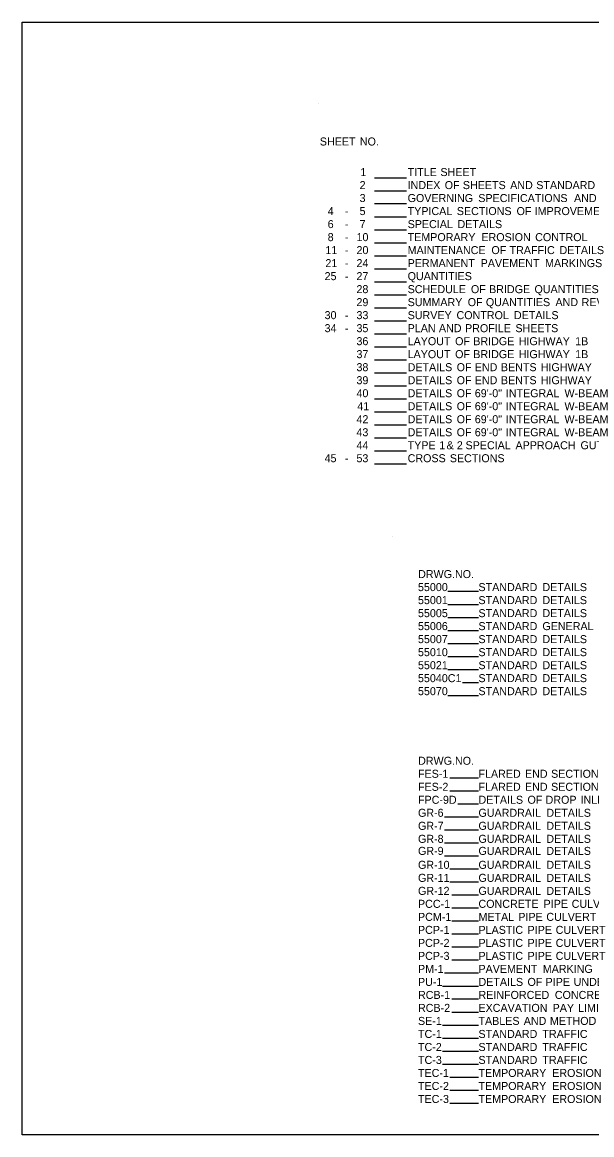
# Model space of a CAD drawing. Extents: x 1955683 to 1956002, y 566394 to 566602.
# Drawn here: x 1955683.4 to 1955790.1, y 566393.5 to 566602 of the extents above; entities that cross this region are included whole.
import ezdxf

# ---------------------------------------------------------------- set-up
doc = ezdxf.new("R2010")
doc.units = 0
doc.layers.add('Default', color=7, linetype='Continuous')
doc.layers.add('R_Border Prem', color=7, linetype='Continuous')

msp = doc.modelspace()

# ---------------------------------------------------------------- linework, layer by layer
at = {"layer": 'Default'}
for p, q in [((1955738.89, 566586.74), (1955738.89, 566586.74)), ((1955749.37, 566572.85), (1955755.35, 566572.85)), ((1955749.37, 566570.41), (1955755.35, 566570.41)), ((1955749.37, 566567.98), (1955755.35, 566567.98)), ((1955749.37, 566565.54), (1955755.35, 566565.54)), ((1955749.37, 566563.1), (1955755.35, 566563.1)), ((1955749.37, 566560.66), (1955755.35, 566560.66)), ((1955749.37, 566558.23), (1955755.35, 566558.23)), ((1955749.37, 566555.79), (1955755.35, 566555.79)), ((1955749.37, 566553.35), (1955755.35, 566553.35)), ((1955749.37, 566550.91), (1955755.35, 566550.91)), ((1955749.37, 566548.48), (1955755.35, 566548.48)), ((1955749.37, 566546.04), (1955755.35, 566546.04)), ((1955749.37, 566543.6), (1955755.35, 566543.6)), ((1955749.37, 566541.16), (1955755.35, 566541.16)), ((1955749.37, 566538.73), (1955755.35, 566538.73)), ((1955749.37, 566536.29), (1955755.35, 566536.29)), ((1955749.37, 566533.85), (1955755.35, 566533.85)), ((1955749.37, 566531.41), (1955755.35, 566531.41)), ((1955749.37, 566528.98), (1955755.35, 566528.98)), ((1955749.37, 566526.54), (1955755.35, 566526.54)), ((1955749.37, 566524.1), (1955755.35, 566524.1)), ((1955749.37, 566521.66), (1955755.35, 566521.66)), ((1955749.37, 566519.23), (1955755.35, 566519.23)), ((1955752.77, 566505.68), (1955752.77, 566505.68)), ((1955763.1, 566495.34), (1955768.86, 566495.34)), ((1955763.1, 566492.9), (1955768.86, 566492.9)), ((1955763.1, 566490.46), (1955768.86, 566490.46)), ((1955763.1, 566488.02), (1955768.86, 566488.02)), ((1955763.1, 566485.59), (1955768.86, 566485.59)), ((1955763.1, 566483.15), (1955768.86, 566483.15)), ((1955763.1, 566480.71), (1955768.86, 566480.71)), ((1955765.85, 566478.27), (1955768.86, 566478.27)), ((1955763.1, 566475.84), (1955768.86, 566475.84)), ((1955763.47, 566460.38), (1955768.86, 566460.38)), ((1955763.47, 566457.95), (1955768.86, 566457.95)), ((1955764.98, 566455.51), (1955768.86, 566455.51)), ((1955762.51, 566453.07), (1955768.86, 566453.07)), ((1955762.51, 566450.63), (1955768.86, 566450.63)), ((1955762.51, 566448.2), (1955768.86, 566448.2)), ((1955762.51, 566445.76), (1955768.86, 566445.76)), ((1955763.47, 566443.32), (1955768.86, 566443.32)), ((1955763.47, 566440.88), (1955768.86, 566440.88)), ((1955763.87, 566438.45), (1955768.86, 566438.45)), ((1955763.87, 566436.01), (1955768.86, 566436.01)), ((1955763.87, 566433.57), (1955768.86, 566433.57)), ((1955763.87, 566431.13), (1955768.86, 566431.13)), ((1955763.87, 566428.7), (1955768.86, 566428.7)), ((1955763.87, 566426.26), (1955768.86, 566426.26)), ((1955762.51, 566423.82), (1955768.86, 566423.82)), ((1955762.13, 566421.38), (1955768.86, 566421.38)), ((1955763.87, 566418.95), (1955768.86, 566418.95)), ((1955763.87, 566416.51), (1955768.86, 566416.51)), ((1955762.13, 566414.07), (1955768.86, 566414.07)), ((1955762.13, 566411.63), (1955768.86, 566411.63)), ((1955762.13, 566409.2), (1955768.86, 566409.2)), ((1955762.13, 566406.76), (1955768.86, 566406.76)), ((1955763.47, 566404.32), (1955768.86, 566404.32)), ((1955763.47, 566401.88), (1955768.86, 566401.88)), ((1955763.47, 566399.45), (1955768.86, 566399.45))]:
    msp.add_line(p, q, dxfattribs=at)
at = {"layer": 'R_Border Prem'}
msp.add_lwpolyline([(1956002.45, 566561.79), (1956002.45, 566393.51), (1955683.38, 566393.51), (1955683.38, 566601.97), (1955920.19, 566601.97), (1955920.19, 566592.09), (1955955.71, 566592.09), (1955955.71, 566588.52), (1955959.35, 566588.52), (1955959.35, 566589.17), (1955974.89, 566589.17)], dxfattribs=at)

# ---------------------------------------------------------------- texts
at = {"layer": 'Default'}
for s, p in [('SHEET', (1955739.14, 566578.88)), (' NO.', (1955746.08, 566578.88)), ('1', (1955746.73, 566573.15)), ('TITLE', (1955755.59, 566573.15)), (' SHEET', (1955761.18, 566573.15)), ('2', (1955746.59, 566570.71)), ('INDEX', (1955755.59, 566570.71)), (' OF', (1955761.98, 566570.71)), (' SHEETS', (1955765.38, 566570.71)), (' AND', (1955774.24, 566570.71)), (' STANDARD', (1955779.13, 566570.71)), ('3', (1955746.59, 566568.28)), ('GOVERNING', (1955755.59, 566568.28)), (' SPECIFICATIONS', (1955768.27, 566568.28)), (' AND', (1955786.21, 566568.28)), ('4', (1955740.62, 566565.84)), ('-', (1955743.82, 566565.84)), ('5', (1955746.58, 566565.84)), ('TYPICAL', (1955755.59, 566565.84)), (' SECTIONS', (1955764.25, 566565.84)), (' OF', (1955775.44, 566565.84)), (' IMPROVEMENT', (1955778.84, 566565.84)), ('6', (1955740.61, 566563.4)), ('7', (1955746.59, 566563.4)), ('SPECIAL', (1955755.59, 566563.4)), (' DETAILS', (1955764.37, 566563.4)), ('8', (1955740.61, 566560.96)), ('-', (1955743.82, 566563.4)), ('10', (1955746.01, 566560.96)), ('TEMPORARY', (1955755.59, 566560.96)), (' EROSION', (1955768.85, 566560.96)), (' CONTROL', (1955778.93, 566560.96)), ('-', (1955743.82, 566560.96)), ('11', (1955740.18, 566558.53)), ('-', (1955743.82, 566558.53)), ('20', (1955746.01, 566558.53)), ('MAINTENANCE', (1955755.59, 566558.53)), (' OF', (1955770.73, 566558.53)), (' TRAFFIC', (1955774.13, 566558.53)), (' DETAILS', (1955783.48, 566558.53)), ('21', (1955740.18, 566556.09)), ('-', (1955743.82, 566556.09)), ('24', (1955746.01, 566556.09)), ('PERMANENT', (1955755.59, 566556.09)), (' PAVEMENT', (1955768.71, 566556.09)), (' MARKINGS', (1955780.78, 566556.09)), ('25', (1955740.03, 566553.65)), ('-', (1955743.82, 566553.65)), ('27', (1955746, 566553.65)), ('QUANTITIES', (1955755.59, 566553.65)), ('28', (1955746, 566551.21)), ('SCHEDULE', (1955755.59, 566551.21)), (' OF', (1955766.89, 566551.21)), (' BRIDGE', (1955770.29, 566551.21)), (' QUANTITIES', (1955778.8, 566551.21)), ('29', (1955746, 566548.78)), ('SUMMARY', (1955755.59, 566548.78)), (' OF', (1955766.29, 566548.78)), (' QUANTITIES', (1955769.69, 566548.78)), (' AND', (1955782.73, 566548.78)), (' REVISIONS', (1955787.63, 566548.78)), ('30', (1955740.03, 566546.34)), ('33', (1955746, 566546.34)), ('SURVEY', (1955755.59, 566546.34)), (' CONTROL', (1955764.19, 566546.34)), (' DETAILS', (1955774.95, 566546.34)), ('-', (1955743.82, 566546.34)), ('34', (1955740.03, 566543.9)), ('-', (1955743.82, 566543.9)), ('35', (1955746, 566543.9)), ('PLAN', (1955755.59, 566543.9)), (' AND', (1955760.89, 566543.9)), (' PROFILE', (1955765.79, 566543.9)), (' SHEETS', (1955775.23, 566543.9)), ('36', (1955746, 566541.46)), ('LAYOUT', (1955755.59, 566541.46)), (' OF', (1955763.93, 566541.46)), (' BRIDGE', (1955767.33, 566541.46)), (' HIGHWAY', (1955775.84, 566541.46)), (' 1B', (1955786.42, 566541.46)), ('37', (1955746, 566539.03)), ('LAYOUT', (1955755.59, 566539.03)), (' OF', (1955763.93, 566539.03)), (' BRIDGE', (1955767.33, 566539.03)), (' HIGHWAY', (1955775.84, 566539.03)), (' 1B', (1955786.42, 566539.03)), ('38', (1955746, 566536.59)), ('DETAILS', (1955755.59, 566536.59)), (' OF', (1955764.22, 566536.59)), (' END', (1955767.61, 566536.59)), (' BENTS', (1955772.51, 566536.59)), (' HIGHWAY', (1955779.97, 566536.59)), ('39', (1955746, 566534.15)), ('DETAILS', (1955755.59, 566534.15)), (' OF', (1955764.22, 566534.15)), (' END', (1955767.61, 566534.15)), (' BENTS', (1955772.51, 566534.15)), (' HIGHWAY', (1955779.97, 566534.15)), ('40', (1955746.01, 566531.71)), ('DETAILS', (1955755.59, 566531.71)), (' OF', (1955764.22, 566531.71)), (' 69\'-0"', (1955767.61, 566531.71)), (' INTEGRAL', (1955773.43, 566531.71)), (' W-BEAM', (1955784.42, 566531.71)), ('41', (1955746.15, 566529.28)), ('DETAILS', (1955755.59, 566529.28)), (' OF', (1955764.22, 566529.28)), (' 69\'-0"', (1955767.61, 566529.28)), (' INTEGRAL', (1955773.43, 566529.28)), (' W-BEAM', (1955784.42, 566529.28)), ('42', (1955746.01, 566526.84)), ('DETAILS', (1955755.59, 566526.84)), (' OF', (1955764.22, 566526.84)), (' 69\'-0"', (1955767.61, 566526.84)), (' INTEGRAL', (1955773.43, 566526.84)), (' W-BEAM', (1955784.42, 566526.84)), ('43', (1955746, 566524.4)), ('DETAILS', (1955755.59, 566524.4)), (' OF', (1955764.22, 566524.4)), (' 69\'-0"', (1955767.61, 566524.4)), (' INTEGRAL', (1955773.43, 566524.4)), (' W-BEAM', (1955784.42, 566524.4)), ('44', (1955746.01, 566521.96)), ('TYPE', (1955755.59, 566521.96)), (' 1', (1955760.95, 566521.96)), (' &', (1955762.32, 566521.96)), (' 2', (1955764.25, 566521.96)), (' SPECIAL', (1955765.88, 566521.96)), (' APPROACH', (1955775.24, 566521.96)), (' GUTTERS', (1955787.42, 566521.96)), ('45', (1955740.03, 566519.53)), ('53', (1955746, 566519.53)), ('CROSS', (1955755.59, 566519.53)), (' SECTIONS', (1955762.94, 566519.53)), ('-', (1955743.82, 566519.53)), ('DRWG.NO.', (1955757.55, 566497.82)), ('55000', (1955757.53, 566495.38)), ('STANDARD', (1955768.86, 566495.38)), (' DETAILS', (1955780.28, 566495.38)), ('55001', (1955757.53, 566492.94)), ('STANDARD', (1955768.86, 566492.94)), (' DETAILS', (1955780.28, 566492.94)), ('55005', (1955757.53, 566490.5)), ('STANDARD', (1955768.86, 566490.5)), (' DETAILS', (1955780.28, 566490.5)), ('55006', (1955757.53, 566488.07)), ('STANDARD', (1955768.86, 566488.07)), (' GENERAL', (1955780.28, 566488.07)), ('55007', (1955757.53, 566485.63)), ('STANDARD', (1955768.86, 566485.63)), (' DETAILS', (1955780.28, 566485.63)), ('55010', (1955757.53, 566483.19)), ('STANDARD', (1955768.86, 566483.19)), (' DETAILS', (1955780.28, 566483.19)), ('55021', (1955757.53, 566480.75)), ('STANDARD', (1955768.86, 566480.75)), (' DETAILS', (1955780.28, 566480.75)), ('55040C1', (1955757.53, 566478.32)), ('STANDARD', (1955768.86, 566478.32)), (' DETAILS', (1955780.28, 566478.32)), ('55070', (1955757.53, 566475.88)), ('STANDARD', (1955768.86, 566475.88)), (' DETAILS', (1955780.28, 566475.88)), ('DRWG.NO.', (1955757.55, 566462.84)), ('FES-1', (1955757.53, 566460.4)), ('FLARED', (1955768.86, 566460.4)), (' END', (1955777.02, 566460.4)), (' SECTION', (1955781.91, 566460.4)), ('FES-2', (1955757.53, 566457.96)), ('FLARED', (1955768.86, 566457.96)), (' END', (1955777.02, 566457.96)), (' SECTION', (1955781.91, 566457.96)), ('FPC-9D', (1955757.53, 566455.53)), ('DETAILS', (1955768.86, 566455.53)), (' OF', (1955777.49, 566455.53)), (' DROP', (1955780.88, 566455.53)), (' INLETS', (1955787.43, 566455.53)), ('GR-6', (1955757.53, 566453.09)), ('GUARDRAIL', (1955768.86, 566453.09)), (' DETAILS', (1955781.02, 566453.09)), ('GR-7', (1955757.53, 566450.65)), ('GUARDRAIL', (1955768.86, 566450.65)), (' DETAILS', (1955781.02, 566450.65)), ('GR-8', (1955757.53, 566448.21)), ('GUARDRAIL', (1955768.86, 566448.21)), (' DETAILS', (1955781.02, 566448.21)), ('GR-9', (1955757.53, 566445.95)), ('GUARDRAIL', (1955768.86, 566445.95)), (' DETAILS', (1955781.02, 566445.95)), ('GR-10', (1955757.53, 566443.34)), ('GUARDRAIL', (1955768.86, 566443.34)), (' DETAILS', (1955781.02, 566443.34)), ('GR-11', (1955757.53, 566440.9)), ('GUARDRAIL', (1955768.86, 566440.9)), (' DETAILS', (1955781.02, 566440.9)), ('GR-12', (1955757.53, 566438.46)), ('GUARDRAIL', (1955768.86, 566438.46)), (' DETAILS', (1955781.02, 566438.46)), ('PCC-1', (1955757.53, 566436.03)), ('CONCRETE', (1955768.86, 566436.03)), (' PIPE', (1955780.51, 566436.03)), (' CULVERT', (1955785.76, 566436.03)), ('PCM-1', (1955757.53, 566433.59)), ('METAL', (1955768.86, 566433.59)), (' PIPE', (1955775.77, 566433.59)), (' CULVERT', (1955781.02, 566433.59)), ('PCP-1', (1955757.53, 566431.15)), ('PLASTIC', (1955768.86, 566431.15)), (' PIPE', (1955777.51, 566431.15)), (' CULVERT', (1955782.76, 566431.15)), ('PCP-2', (1955757.53, 566428.71)), ('PLASTIC', (1955768.86, 566428.71)), (' PIPE', (1955777.51, 566428.71)), (' CULVERT', (1955782.76, 566428.71)), ('PCP-3', (1955757.53, 566426.28)), ('PLASTIC', (1955768.86, 566426.28)), (' PIPE', (1955777.51, 566426.28)), (' CULVERT', (1955782.76, 566426.28)), ('PM-1', (1955757.53, 566423.84)), ('PAVEMENT', (1955768.86, 566423.84)), (' MARKING', (1955780.35, 566423.84)), ('PU-1', (1955757.53, 566421.4)), ('DETAILS', (1955768.86, 566421.4)), (' OF', (1955777.49, 566421.4)), (' PIPE', (1955780.88, 566421.4)), (' UNDERDRAIN', (1955786.13, 566421.4)), ('RCB-1', (1955757.53, 566418.96)), ('REINFORCED', (1955768.86, 566418.96)), (' CONCRETE', (1955782.61, 566418.96)), ('RCB-2', (1955757.53, 566416.53)), ('EXCAVATION', (1955768.86, 566416.53)), (' PAY', (1955782.2, 566416.53)), (' LIMITS,', (1955786.96, 566416.53)), ('SE-1', (1955757.53, 566414.09)), ('TABLES', (1955768.86, 566414.09)), (' AND', (1955776.79, 566414.09)), (' METHOD', (1955781.69, 566414.09)), ('TC-1', (1955757.53, 566411.65)), ('STANDARD', (1955768.86, 566411.65)), (' TRAFFIC', (1955780.28, 566411.65)), ('TC-2', (1955757.53, 566409.21)), ('STANDARD', (1955768.86, 566409.21)), (' TRAFFIC', (1955780.28, 566409.21)), ('TC-3', (1955757.53, 566406.78)), ('STANDARD', (1955768.86, 566406.78)), (' TRAFFIC', (1955780.28, 566406.78)), ('TEC-1', (1955757.53, 566404.34)), ('TEMPORARY', (1955768.86, 566404.34)), (' EROSION', (1955782.12, 566404.34)), ('TEC-2', (1955757.53, 566401.9)), ('TEMPORARY', (1955768.86, 566401.9)), (' EROSION', (1955782.12, 566401.9)), ('TEC-3', (1955757.53, 566399.46)), ('TEMPORARY', (1955768.86, 566399.46)), (' EROSION', (1955782.12, 566399.46))]:
    msp.add_text(s, height=1.5, dxfattribs=at).set_placement(p)

doc.saveas('drawing.dxf')
